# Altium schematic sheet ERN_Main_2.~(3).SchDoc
size A; SheetNumber: 2; SheetTotal: 2; SPICEModelCacheYVUKJMZF: <root> / <DocumentId>YVUKJMZF</DocumentId> / <CacheFrame Number="0"> / <Model Name="1n5400" Kind="MDL"> / <Text>*1N5400 MCE / * 50V 3A Si Rectifier pkg:DO-201 1,2 / .MODEL 1N5400 D(IS=2.68E-12 RS=0.00977 N=1.17 TT=1.44E-5 CJO=1.24E-10 / + VJ=0.6 M=0.333 BV=66.6 IBV=1E-5 )</Text> / </Model> / <Model Name="led2" Kind="MDL"> / <Text>*Typ RED,GREEN,YELLOW,AMBER GaAs LED: Vf=2.1V Vr=4V If=40mA trr=3uS / *LED Pinout: 1=A, 2=K / .MODEL LED2 D (IS=93.1P RS=42M N=4.61 BV=4 IBV=10U / + CJO=2.97P VJ=.75 M=.333 TT=4.32U)</Text> / </Model> / </CacheFrame> / </root>
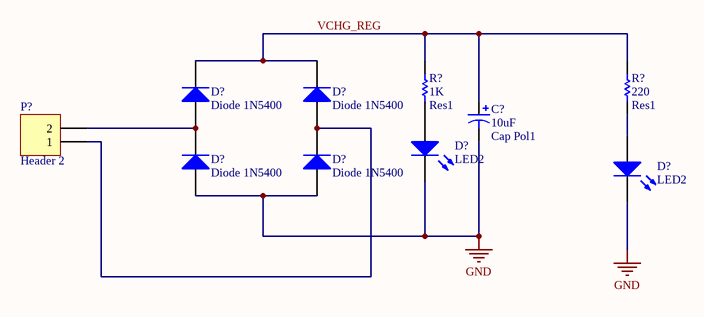
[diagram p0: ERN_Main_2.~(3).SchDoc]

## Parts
(Parts that share a designator on the sheet are numbered #1, #2 ... from top to bottom, then left to right.)
C?  Cap Pol1  value 10uF  [RB7.6-15]
D?#1  Diode 1N5400  [DO-201AD]
D?#2  Diode 1N5400  [DO-201AD]
D?#3  LED2  [3.2X1.6X1.1]
D?#4  LED2  [3.2X1.6X1.1]
D?#5  Diode 1N5400  [DO-201AD]
D?#6  Diode 1N5400  [DO-201AD]
P?  Header 2  [HDR1X2]
R?#1  Res1  value 1K  [AXIAL-0.3]
R?#2  Res1  value 220  [AXIAL-0.3]

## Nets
GND: C?.2 D?#3.2(K) D?#4.2(K) D?#5.1(A) D?#6.1(A)
VCHG_REG: C?.1 D?#1.2(K) D?#2.2(K) R?#1.2 R?#2.2
NetD?#1_1: D?#1.1(A) D?#5.2(K) P?.2
NetD?#2_1: D?#2.1(A) D?#6.2(K) P?.1
NetD?#3_1: D?#3.1(A) R?#1.1
NetD?#4_1: D?#4.1(A) R?#2.1

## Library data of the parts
C? = Cap Pol1: Polarized Capacitor (Radial)
D?#1 D?#2 D?#5 D?#6 = Diode 1N5400: 3 Amp General Purpose Rectifier
D?#3 D?#4 = LED2: Typical RED, GREEN, YELLOW, AMBER GaAs LED
P? = Header 2: Header, 2-Pin
R?#1 R?#2 = Res1: Resistor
